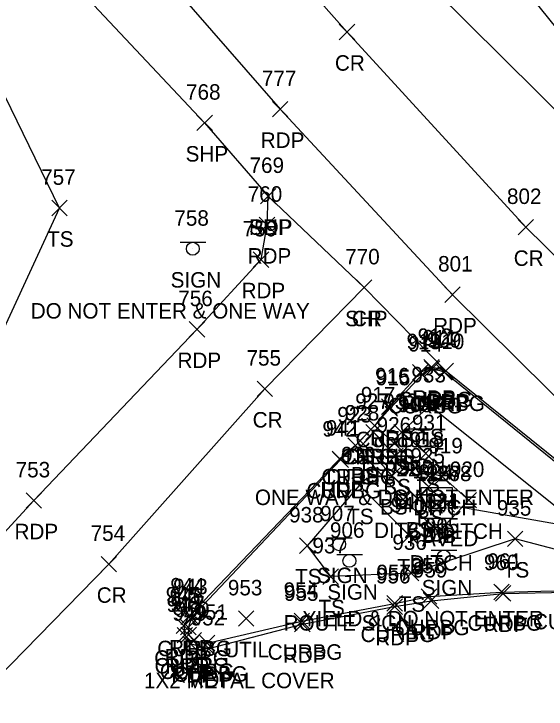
# Model space of a CAD drawing. Extents: x 1688195 to 1692013, y 424605 to 441234.
# Drawn here: x 1691718.1 to 1691786.9, y 439243.2 to 439333.1 of the extents above; entities that cross this region are included whole.
import ezdxf

# ---------------------------------------------------------------- set-up
doc = ezdxf.new("R2010")
doc.units = 0
for name, color, linetype in [('D_A', 7, 'Continuous'), ('D_C', 7, 'Continuous'), ('D_I', 7, 'Continuous'), ('D_TIC', 7, 'Continuous'), ('DCP', 7, 'Continuous'), ('DD', 7, 'Continuous'), ('DS', 7, 'Continuous'), ('L_A', 7, 'Continuous'), ('L_I', 7, 'Continuous'), ('L_TIC', 7, 'Continuous'), ('LELB', 7, 'Continuous'), ('P_A', 7, 'Continuous'), ('P_I', 7, 'Continuous'), ('P_TIC', 7, 'Continuous'), ('PET', 7, 'Continuous'), ('PRC', 7, 'Continuous'), ('PSP', 7, 'Continuous'), ('R_A', 7, 'Continuous'), ('R_I', 7, 'Continuous'), ('R_TIC', 7, 'Continuous'), ('RC', 7, 'Continuous'), ('S_A', 7, 'Continuous'), ('S_C', 7, 'Continuous'), ('S_I', 7, 'Continuous'), ('SSGN', 7, 'Continuous'), ('U_A', 7, 'Continuous'), ('U_C', 7, 'Continuous'), ('U_I', 7, 'Continuous'), ('UDEFAULT', 7, 'Continuous')]:
    doc.layers.add(name, color=color, linetype=linetype)

msp = doc.modelspace()

# ---------------------------------------------------------------- linework, layer by layer
at = {"layer": 'D_TIC'}
for points in [[(1691763.751, 439278.868), (1691765.751, 439280.868)], [(1691765.751, 439278.868), (1691763.751, 439280.868)], [(1691761.264, 439276.277), (1691763.264, 439278.277)], [(1691763.264, 439276.277), (1691761.264, 439278.277)], [(1691770.071, 439273.049), (1691772.071, 439275.049)], [(1691772.071, 439273.049), (1691770.071, 439275.049)], [(1691772.498, 439272.277), (1691774.498, 439274.277)], [(1691774.498, 439272.277), (1691772.498, 439274.277)], [(1691767.428, 439269.325), (1691769.428, 439271.325)], [(1691769.428, 439269.325), (1691767.428, 439271.325)], [(1691775.925, 439269.225), (1691777.925, 439271.225)], [(1691777.925, 439269.225), (1691775.925, 439271.225)], [(1691771.74, 439268.698), (1691773.74, 439270.698)], [(1691773.74, 439268.698), (1691771.74, 439270.698)], [(1691773.059, 439268.686), (1691775.059, 439270.686)], [(1691775.059, 439268.686), (1691773.059, 439270.686)], [(1691772.039, 439265.126), (1691774.039, 439267.126)], [(1691774.039, 439265.126), (1691772.039, 439267.126)]]:
    msp.add_lwpolyline(points, dxfattribs=at)
at = {"layer": 'DCP'}
msp.add_lwpolyline([(1691774.059, 439269.686), (1691869.305, 439252.966)], dxfattribs=at)
at = {"layer": 'DD'}
msp.add_lwpolyline([(1691764.751, 439279.868), (1691771.071, 439274.049), (1691773.498, 439273.277), (1691776.925, 439270.225), (1691773.039, 439266.126), (1691768.428, 439270.325), (1691762.264, 439277.277)], dxfattribs=at)
at = {"layer": 'DS'}
for p, q in [((1691770.781, 439271.862), (1691774.781, 439271.862)), ((1691770.781, 439267.862), (1691770.781, 439271.862)), ((1691774.781, 439271.862), (1691774.781, 439267.862)), ((1691771.781, 439268.862), (1691771.781, 439270.862)), ((1691771.781, 439270.862), (1691773.781, 439270.862)), ((1691773.781, 439270.862), (1691773.781, 439268.862)), ((1691772.786, 439269.864), (1691772.786, 439269.864)), ((1691772.786, 439269.864), (1691772.786, 439269.864)), ((1691773.781, 439268.862), (1691771.781, 439268.862)), ((1691774.781, 439267.862), (1691770.781, 439267.862))]:
    msp.add_line(p, q, dxfattribs=at)
at = {"layer": 'L_TIC'}
for points in [[(1691722.954, 439306.993), (1691724.954, 439308.993)], [(1691724.954, 439306.993), (1691722.954, 439308.993)], [(1691770.864, 439281.457), (1691772.864, 439283.457)], [(1691772.864, 439281.457), (1691770.864, 439283.457)], [(1691763.594, 439278.02), (1691765.594, 439280.02)], [(1691765.594, 439278.02), (1691763.594, 439280.02)], [(1691767.238, 439278.008), (1691769.238, 439280.008)], [(1691769.238, 439278.008), (1691767.238, 439280.008)], [(1691762.245, 439276.524), (1691764.245, 439278.524)], [(1691764.245, 439276.524), (1691762.245, 439278.524)], [(1691766.417, 439274.97), (1691768.417, 439276.97)], [(1691768.417, 439274.97), (1691766.417, 439276.97)], [(1691770.366, 439275.277), (1691772.366, 439277.277)], [(1691772.366, 439275.277), (1691770.366, 439277.277)], [(1691766.002, 439272.378), (1691768.002, 439274.378)], [(1691768.002, 439272.378), (1691766.002, 439274.378)], [(1691761.781, 439271.129), (1691763.781, 439273.129)], [(1691763.781, 439271.129), (1691761.781, 439273.129)], [(1691770.738, 439270.968), (1691772.738, 439272.968)], [(1691772.738, 439270.968), (1691770.738, 439272.968)], [(1691770.738, 439270.968), (1691772.738, 439272.968)], [(1691772.738, 439270.968), (1691770.738, 439272.968)], [(1691769.317, 439269.425), (1691771.317, 439271.425)], [(1691771.317, 439269.425), (1691769.317, 439271.425)], [(1691769.317, 439269.425), (1691771.317, 439271.425)], [(1691771.317, 439269.425), (1691769.317, 439271.425)], [(1691768.275, 439264.641), (1691770.275, 439266.641)], [(1691770.275, 439264.641), (1691768.275, 439266.641)], [(1691781.923, 439264.227), (1691783.923, 439266.227)], [(1691783.923, 439264.227), (1691781.923, 439266.227)], [(1691755.036, 439263.348), (1691757.036, 439265.348)], [(1691757.036, 439263.348), (1691755.036, 439265.348)], [(1691758.054, 439259.351), (1691760.054, 439261.351)], [(1691760.054, 439259.351), (1691758.054, 439261.351)], [(1691768.459, 439259.809), (1691770.459, 439261.809)], [(1691770.459, 439259.809), (1691768.459, 439261.809)]]:
    msp.add_lwpolyline(points, dxfattribs=at)
at = {"layer": 'LELB'}
for points in [[(1691372.727, 438902.639), (1691398.565, 438929.628), (1691421.613, 438954.811), (1691450.498, 438984.078), (1691477.459, 439013.336), (1691508.259, 439046.519), (1691540.849, 439082.44), (1691568.309, 439110.724), (1691593.687, 439141.207), (1691622.929, 439171.735), (1691652.839, 439206.763), (1691674.707, 439229.191), (1691701.219, 439256.482), (1691710.89, 439279.749), (1691723.954, 439307.993), (1691712.174, 439332.073), (1691693.939, 439358.264), (1691684.004, 439373.025)], [(1691771.366, 439276.277), (1691768.238, 439279.008), (1691771.864, 439282.457), (1691798.546, 439261.132), (1691782.923, 439265.227), (1691769.459, 439260.809), (1691759.054, 439260.351), (1691756.036, 439264.348), (1691762.781, 439272.129), (1691769.275, 439265.641)], [(1691771.738, 439271.968), (1691767.417, 439275.97), (1691764.594, 439279.02), (1691763.245, 439277.524), (1691767.002, 439273.378), (1691770.317, 439270.425)], [(1691771.738, 439271.968), (1691770.317, 439270.425)]]:
    msp.add_lwpolyline(points, dxfattribs=at)
at = {"layer": 'P_TIC'}
for points in [[(1691760.172, 439329.745), (1691762.172, 439331.745)], [(1691762.172, 439329.745), (1691760.172, 439331.745)], [(1691751.514, 439319.765), (1691753.514, 439321.765)], [(1691753.514, 439319.765), (1691751.514, 439321.765)], [(1691741.747, 439318), (1691743.747, 439320)], [(1691743.747, 439318), (1691741.747, 439320)], [(1691749.974, 439308.526), (1691751.974, 439310.526)], [(1691751.974, 439308.526), (1691749.974, 439310.526)], [(1691749.974, 439308.526), (1691751.974, 439310.526)], [(1691751.974, 439308.526), (1691749.974, 439310.526)], [(1691749.818, 439304.807), (1691751.818, 439306.807)], [(1691751.818, 439304.807), (1691749.818, 439306.807)], [(1691783.31, 439304.517), (1691785.31, 439306.517)], [(1691785.31, 439304.517), (1691783.31, 439306.517)], [(1691749.039, 439300.327), (1691751.039, 439302.327)], [(1691751.039, 439300.327), (1691749.039, 439302.327)], [(1691762.384, 439296.713), (1691764.384, 439298.713)], [(1691764.384, 439296.713), (1691762.384, 439298.713)], [(1691762.384, 439296.713), (1691764.384, 439298.713)], [(1691764.384, 439296.713), (1691762.384, 439298.713)], [(1691773.827, 439295.788), (1691775.827, 439297.788)], [(1691775.827, 439295.788), (1691773.827, 439297.788)], [(1691740.75, 439291.31), (1691742.75, 439293.31)], [(1691742.75, 439291.31), (1691740.75, 439293.31)], [(1691771.103, 439286.435), (1691773.103, 439288.435)], [(1691773.103, 439286.435), (1691771.103, 439288.435)], [(1691769.661, 439285.747), (1691771.661, 439287.747)], [(1691771.661, 439285.747), (1691769.661, 439287.747)], [(1691772.94, 439285.942), (1691774.94, 439287.942)], [(1691774.94, 439285.942), (1691772.94, 439287.942)], [(1691772.94, 439285.942), (1691774.94, 439287.942)], [(1691774.94, 439285.942), (1691772.94, 439287.942)], [(1691749.527, 439283.621), (1691751.527, 439285.621)], [(1691751.527, 439283.621), (1691749.527, 439285.621)], [(1691765.651, 439281.324), (1691767.651, 439283.324)], [(1691767.651, 439281.324), (1691765.651, 439283.324)], [(1691763.751, 439278.868), (1691765.751, 439280.868)], [(1691765.751, 439278.868), (1691763.751, 439280.868)], [(1691761.264, 439276.277), (1691763.264, 439278.277)], [(1691763.264, 439276.277), (1691761.264, 439278.277)], [(1691759.226, 439274.573), (1691761.226, 439276.573)], [(1691761.226, 439274.573), (1691759.226, 439276.573)], [(1691719.655, 439269.179), (1691721.655, 439271.179)], [(1691721.655, 439269.179), (1691719.655, 439271.179)], [(1691729.355, 439260.963), (1691731.355, 439262.963)], [(1691731.355, 439260.963), (1691729.355, 439262.963)], [(1691780.375, 439257.188), (1691782.375, 439259.188)], [(1691782.375, 439257.188), (1691780.375, 439259.188)], [(1691771.069, 439256.236), (1691773.069, 439258.236)], [(1691773.069, 439256.236), (1691771.069, 439258.236)], [(1691766.334, 439255.47), (1691768.334, 439257.47)], [(1691768.334, 439255.47), (1691766.334, 439257.47)], [(1691739.661, 439254.171), (1691741.661, 439256.171)], [(1691741.661, 439254.171), (1691739.661, 439256.171)], [(1691754.388, 439253.219), (1691756.388, 439255.219)], [(1691756.388, 439253.219), (1691754.388, 439255.219)], [(1691739.072, 439253), (1691741.072, 439255)], [(1691741.072, 439253), (1691739.072, 439255)], [(1691739.179, 439251.79), (1691741.179, 439253.79)], [(1691741.179, 439251.79), (1691739.179, 439253.79)], [(1691739.939, 439250.644), (1691741.939, 439252.644)], [(1691741.939, 439250.644), (1691739.939, 439252.644)], [(1691742.3, 439250.04), (1691744.3, 439252.04)], [(1691744.3, 439250.04), (1691742.3, 439252.04)]]:
    msp.add_lwpolyline(points, dxfattribs=at)
at = {"layer": 'PET'}
for points in [[(1691703.519, 439378.215), (1691727.927, 439348.964), (1691752.514, 439320.765), (1691774.827, 439296.788), (1691803.993, 439267.935), (1691829.698, 439246.009), (1691860.192, 439220.256)], [(1691375.465, 438899.901), (1691401.503, 438927.23), (1691424.189, 438951.439), (1691479.532, 439011.25), (1691510.319, 439044.276), (1691543.268, 439079.533), (1691570.243, 439108.889), (1691596.97, 439137.86), (1691630.016, 439173.336), (1691657.322, 439202.459), (1691678.855, 439225.987), (1691705.087, 439253.29), (1691720.655, 439270.179), (1691741.75, 439292.31), (1691750.039, 439301.327), (1691750.818, 439305.807), (1691750.974, 439309.526)], [(1691773.94, 439286.942), (1691772.103, 439287.435), (1691770.661, 439286.747), (1691766.651, 439282.324), (1691764.751, 439279.868), (1691762.264, 439277.277), (1691760.226, 439275.573), (1691740.661, 439255.171), (1691740.072, 439254), (1691740.179, 439252.79), (1691740.939, 439251.644), (1691743.3, 439251.04), (1691755.388, 439254.219), (1691767.334, 439256.47), (1691772.069, 439257.236), (1691781.375, 439258.188), (1691789.686, 439258.345), (1691799.766, 439257.32), (1691806.846, 439256.861), (1691807.547, 439257.165), (1691807.85, 439258.884), (1691807.317, 439260.152)]]:
    msp.add_lwpolyline(points, dxfattribs=at)
at = {"layer": 'PRC'}
for points in [[(1691721.974, 439394.364), (1691745.645, 439365.634), (1691767.872, 439340.76), (1691794.844, 439314.033)], [(1691713.182, 439386.477), (1691737.313, 439357.714), (1691761.172, 439330.745), (1691784.31, 439305.517), (1691812.134, 439278.202), (1691838.297, 439254.51), (1691867.441, 439230.247), (1691889.259, 439214.415), (1691920.444, 439189.798), (1691954.552, 439163.68)], [(1691799.482, 439317.379), (1691771.685, 439351.898), (1691744.242, 439385.863)], [(1691383.454, 438891.457), (1691410.111, 438918.446), (1691432.707, 438943.441), (1691460.693, 438973.594), (1691487.768, 439002.583), (1691519.39, 439036.11), (1691551.828, 439070.88), (1691579.206, 439100.285), (1691605.825, 439129.375), (1691637.875, 439164.382), (1691665.605, 439193.964), (1691687.962, 439216.916), (1691714.01, 439245.271), (1691730.355, 439261.963), (1691750.527, 439284.621), (1691763.384, 439297.713)]]:
    msp.add_lwpolyline(points, dxfattribs=at)
at = {"layer": 'PSP'}
msp.add_lwpolyline([(1691696.132, 439372.686), (1691709.548, 439355.191), (1691723.603, 439339.325), (1691742.747, 439319), (1691750.974, 439309.526), (1691763.384, 439297.713), (1691773.94, 439286.942), (1691807.317, 439260.152), (1691827.219, 439244.924), (1691853.912, 439221.372)], dxfattribs=at)
at = {"layer": 'R_TIC'}
for points in [[(1691769.891, 439285.445), (1691771.891, 439287.445)], [(1691771.891, 439285.445), (1691769.891, 439287.445)], [(1691771.176, 439286.233), (1691773.176, 439288.233)], [(1691773.176, 439286.233), (1691771.176, 439288.233)], [(1691772.768, 439285.756), (1691774.768, 439287.756)], [(1691774.768, 439285.756), (1691772.768, 439287.756)], [(1691772.768, 439285.756), (1691774.768, 439287.756)], [(1691774.768, 439285.756), (1691772.768, 439287.756)], [(1691765.697, 439281.079), (1691767.697, 439283.079)], [(1691767.697, 439281.079), (1691765.697, 439283.079)], [(1691763.751, 439278.868), (1691765.751, 439280.868)], [(1691765.751, 439278.868), (1691763.751, 439280.868)], [(1691761.264, 439276.277), (1691763.264, 439278.277)], [(1691763.264, 439276.277), (1691761.264, 439278.277)], [(1691759.343, 439274.452), (1691761.343, 439276.452)], [(1691761.343, 439274.452), (1691759.343, 439276.452)], [(1691770.771, 439256.775), (1691772.771, 439258.775)], [(1691772.771, 439256.775), (1691770.771, 439258.775)], [(1691780.171, 439257.359), (1691782.171, 439259.359)], [(1691782.171, 439257.359), (1691780.171, 439259.359)], [(1691766.334, 439255.888), (1691768.334, 439257.888)], [(1691768.334, 439255.888), (1691766.334, 439257.888)], [(1691740.032, 439254.066), (1691742.032, 439256.066)], [(1691742.032, 439254.066), (1691740.032, 439256.066)], [(1691754.326, 439253.607), (1691756.326, 439255.607)], [(1691756.326, 439253.607), (1691754.326, 439255.607)], [(1691739.637, 439252.822), (1691741.637, 439254.822)], [(1691741.637, 439252.822), (1691739.637, 439254.822)], [(1691739.67, 439251.826), (1691741.67, 439253.826)], [(1691741.67, 439251.826), (1691739.67, 439253.826)], [(1691740.357, 439251.113), (1691742.357, 439253.113)], [(1691742.357, 439251.113), (1691740.357, 439253.113)], [(1691742.083, 439250.766), (1691744.083, 439252.766)], [(1691744.083, 439250.766), (1691742.083, 439252.766)]]:
    msp.add_lwpolyline(points, dxfattribs=at)
at = {"layer": 'RC'}
for points in [[(1691773.768, 439286.756), (1691772.176, 439287.233), (1691770.891, 439286.445), (1691766.697, 439282.079), (1691764.751, 439279.868)], [(1691773.768, 439286.756), (1691806.912, 439260.006)], [(1691762.264, 439277.277), (1691760.343, 439275.452), (1691741.032, 439255.066), (1691740.637, 439253.822), (1691740.67, 439252.826), (1691741.357, 439252.113), (1691743.083, 439251.766), (1691755.326, 439254.607), (1691767.334, 439256.888), (1691771.771, 439257.775), (1691781.171, 439258.359), (1691789.646, 439258.537), (1691799.787, 439257.621), (1691806.795, 439257.068), (1691807.286, 439257.282), (1691807.547, 439258.894), (1691806.912, 439260.006)]]:
    msp.add_lwpolyline(points, dxfattribs=at)
at = {"layer": 'SSGN'}
for p, q in [((1691739.563, 439303.56), (1691742.896, 439303.56)), ((1691741.209, 439302.727), (1691741.209, 439302.727)), ((1691768.589, 439279.452), (1691771.922, 439279.452)), ((1691770.236, 439278.619), (1691770.236, 439278.619)), ((1691758.512, 439265.366), (1691761.845, 439265.366)), ((1691760.159, 439264.533), (1691760.159, 439264.533)), ((1691759.831, 439263.221), (1691763.164, 439263.221)), ((1691772.052, 439263.773), (1691775.385, 439263.773)), ((1691761.478, 439262.387), (1691761.478, 439262.387)), ((1691773.699, 439262.94), (1691773.699, 439262.94))]:
    msp.add_line(p, q, dxfattribs=at)
for centre in [(1691741.209, 439302.727), (1691770.236, 439278.619), (1691760.159, 439264.533), (1691761.478, 439262.387), (1691773.699, 439262.94)]:
    msp.add_circle(centre, 0.833, dxfattribs=at)
at = {"layer": 'UDEFAULT'}
for points in [[(1691747.114, 439253.924), (1691749.114, 439255.924)], [(1691749.114, 439253.924), (1691747.114, 439255.924)]]:
    msp.add_lwpolyline(points, dxfattribs=at)

# ---------------------------------------------------------------- texts
at = {"layer": 'D_A'}
for s, p in [('DITCH', (1691760.988, 439274.868)), ('DITCH', (1691758.5, 439272.277)), ('DITCH', (1691767.307, 439269.049)), ('DITCH', (1691769.734, 439268.277)), ('DITCH', (1691764.664, 439265.325)), ('DI', (1691771.841, 439264.864)), ('DITCH', (1691773.161, 439265.225)), ('DIB', (1691770.842, 439264.698)), ('P', (1691773.437, 439264.686)), ('DITCH', (1691769.275, 439261.126))]:
    msp.add_text(s, height=2, dxfattribs=at).set_placement(p)
at = {"layer": 'D_C'}
msp.add_text('PAVED', height=2, dxfattribs=at).set_placement((1691769.081, 439264.277))
at = {"layer": 'D_I'}
for s, p in [('917', (1691762.956, 439282.868)), ('923', (1691759.902, 439280.277)), ('918', (1691769.275, 439277.049)), ('919', (1691771.695, 439276.277)), ('922', (1691766.065, 439273.325)), ('924', (1691770.424, 439272.864)), ('920', (1691774.476, 439273.225)), ('1267', (1691770, 439272.698)), ('1268', (1691771.319, 439272.686)), ('921', (1691771.244, 439269.126))]:
    msp.add_text(s, height=2, dxfattribs=at).set_placement(p)
at = {"layer": 'L_A'}
for s, p in [('TS', (1691722.363, 439302.993)), ('TS', (1691770.273, 439277.457)), ('BS', (1691763.035, 439274.02)), ('TS', (1691766.647, 439274.008)), ('BS', (1691761.686, 439272.524)), ('TS', (1691769.775, 439271.277)), ('BS', (1691765.857, 439270.97)), ('BS', (1691765.443, 439268.378)), ('TS', (1691761.191, 439267.129)), ('BS', (1691770.179, 439266.968)), ('BS', (1691770.179, 439266.968)), ('BS', (1691768.757, 439265.425)), ('BS', (1691768.757, 439265.425)), ('TS', (1691767.684, 439260.641)), ('TS', (1691781.333, 439260.227)), ('TS', (1691754.446, 439259.348)), ('TS', (1691767.869, 439255.809)), ('TS', (1691757.463, 439255.351))]:
    msp.add_text(s, height=2, dxfattribs=at).set_placement(p)
at = {"layer": 'L_I'}
for s, p in [('757', (1691721.592, 439310.993)), ('933', (1691769.502, 439285.457)), ('927', (1691762.232, 439282.02)), ('932', (1691765.875, 439282.008)), ('928', (1691760.883, 439280.524)), ('931', (1691769.571, 439279.277)), ('926', (1691764.999, 439278.97)), ('929', (1691764.632, 439276.378)), ('939', (1691760.411, 439275.129)), ('925', (1691769.376, 439274.968)), ('925', (1691769.376, 439274.968)), ('930', (1691767.868, 439273.425)), ('930', (1691767.868, 439273.425)), ('940', (1691766.826, 439268.641)), ('935', (1691780.561, 439268.227)), ('938', (1691753.674, 439267.348)), ('936', (1691767.042, 439263.809)), ('937', (1691756.691, 439263.351))]:
    msp.add_text(s, height=2, dxfattribs=at).set_placement(p)
at = {"layer": 'P_A'}
for s, p in [('CR', (1691759.605, 439325.745)), ('RDP', (1691750.002, 439315.765)), ('SHP', (1691740.283, 439314)), ('SHP', (1691748.51, 439304.526)), ('RDP', (1691748.463, 439304.526)), ('RDP', (1691748.307, 439300.807)), ('CR', (1691782.743, 439300.517)), ('RDP', (1691747.527, 439296.327)), ('SHP', (1691760.919, 439292.713)), ('CR', (1691761.817, 439292.713)), ('RDP', (1691772.316, 439291.788)), ('RDP', (1691739.238, 439287.31)), ('RDP', (1691769.591, 439282.435)), ('SHP', (1691771.475, 439281.942)), ('RDP', (1691771.428, 439281.942)), ('RDP', (1691768.149, 439281.747)), ('CR', (1691748.96, 439279.621)), ('RDP', (1691764.14, 439277.324)), ('RDP', (1691762.24, 439274.868)), ('RDP', (1691759.752, 439272.277)), ('RDP', (1691757.715, 439270.573)), ('RDP', (1691718.143, 439265.179)), ('CR', (1691728.788, 439256.963)), ('RDP', (1691778.864, 439253.188)), ('RDP', (1691769.557, 439252.236)), ('RDP', (1691764.822, 439251.47)), ('RDP', (1691738.149, 439250.171)), ('RDP', (1691737.561, 439249)), ('RDP', (1691752.876, 439249.219)), ('RDP', (1691737.668, 439247.79)), ('RDP', (1691738.427, 439246.644)), ('RDP', (1691740.789, 439246.04))]:
    msp.add_text(s, height=2, dxfattribs=at).set_placement(p)
at = {"layer": 'P_I'}
for s, p in [('777', (1691750.152, 439323.765)), ('768', (1691740.338, 439322)), ('769', (1691748.557, 439312.526)), ('769', (1691748.557, 439312.526)), ('760', (1691748.322, 439308.807)), ('802', (1691781.869, 439308.517)), ('759', (1691747.669, 439304.327)), ('770', (1691760.935, 439300.713)), ('770', (1691760.935, 439300.713)), ('801', (1691772.953, 439299.788)), ('756', (1691739.333, 439295.31)), ('912', (1691770.308, 439290.435)), ('909', (1691771.491, 439289.942)), ('909', (1691771.491, 439289.942)), ('913', (1691768.866, 439289.747)), ('755', (1691748.165, 439287.621)), ('916', (1691764.801, 439285.324)), ('917', (1691762.956, 439282.868)), ('923', (1691759.902, 439280.277)), ('941', (1691758.431, 439278.573)), ('753', (1691718.293, 439273.179)), ('754', (1691727.993, 439264.963)), ('960', (1691778.879, 439261.188)), ('959', (1691769.698, 439260.236)), ('956', (1691764.917, 439259.47)), ('944', (1691738.298, 439258.171)), ('945', (1691737.71, 439257)), ('955', (1691753.026, 439257.219)), ('948', (1691737.817, 439255.79)), ('949', (1691738.569, 439254.644)), ('952', (1691740.938, 439254.04))]:
    msp.add_text(s, height=2, dxfattribs=at).set_placement(p)
at = {"layer": 'R_A'}
for p in [(1691767.759, 439282.233), (1691766.473, 439281.445), (1691769.351, 439281.756), (1691769.351, 439281.756), (1691762.28, 439277.079), (1691760.334, 439274.868), (1691757.847, 439272.277), (1691755.925, 439270.452), (1691776.754, 439253.359), (1691785.229, 439253.537), (1691767.354, 439252.775), (1691762.917, 439251.888), (1691736.614, 439250.066), (1691750.909, 439249.607), (1691736.22, 439248.822), (1691736.253, 439247.826), (1691736.94, 439247.113), (1691738.666, 439246.766)]:
    msp.add_text('CURBG', height=2, dxfattribs=at).set_placement(p)
at = {"layer": 'R_I'}
for s, p in [('911', (1691770.948, 439290.233)), ('914', (1691769.095, 439289.445)), ('910', (1691771.886, 439289.756)), ('910', (1691771.886, 439289.756)), ('915', (1691764.902, 439285.079)), ('917', (1691762.956, 439282.868)), ('923', (1691759.902, 439280.277)), ('942', (1691757.98, 439278.452)), ('961', (1691779.329, 439261.359)), ('958', (1691769.409, 439260.775)), ('957', (1691764.972, 439259.888)), ('943', (1691738.669, 439258.066)), ('954', (1691752.964, 439257.607)), ('946', (1691738.22, 439256.822)), ('947', (1691738.308, 439255.826)), ('950', (1691738.908, 439255.113)), ('951', (1691741.288, 439254.766))]:
    msp.add_text(s, height=2, dxfattribs=at).set_placement(p)
at = {"layer": 'S_A'}
for p in [(1691738.347, 439297.706), (1691767.374, 439273.599), (1691757.297, 439259.513), (1691770.836, 439257.92), (1691758.616, 439257.367)]:
    msp.add_text('SIGN', height=2, dxfattribs=at).set_placement(p)
at = {"layer": 'S_C'}
for s, p in [('DO NOT ENTER & ONE WAY', (1691720.245, 439293.706)), ('ONE WAY & DO NOT ENTER', (1691749.248, 439269.599)), ('YIELD & DO NOT ENTER', (1691755.419, 439253.92)), ('ROUTE SIGN', (1691752.962, 439253.367))]:
    msp.add_text(s, height=2, dxfattribs=at).set_placement(p)
at = {"layer": 'S_I'}
for s, p in [('758', (1691738.828, 439305.706)), ('908', (1691767.775, 439281.599)), ('907', (1691757.698, 439267.513)), ('905', (1691771.238, 439265.92)), ('906', (1691758.962, 439265.367))]:
    msp.add_text(s, height=2, dxfattribs=at).set_placement(p)
at = {"layer": 'U_A'}
msp.add_text('UTIL', height=2, dxfattribs=at).set_placement((1691745.279, 439249.924))
at = {"layer": 'U_C'}
msp.add_text('1X2 METAL COVER', height=2, dxfattribs=at).set_placement((1691734.893, 439245.924))
at = {"layer": 'U_I'}
msp.add_text('953', height=2, dxfattribs=at).set_placement((1691745.751, 439257.924))

doc.saveas('drawing.dxf')
